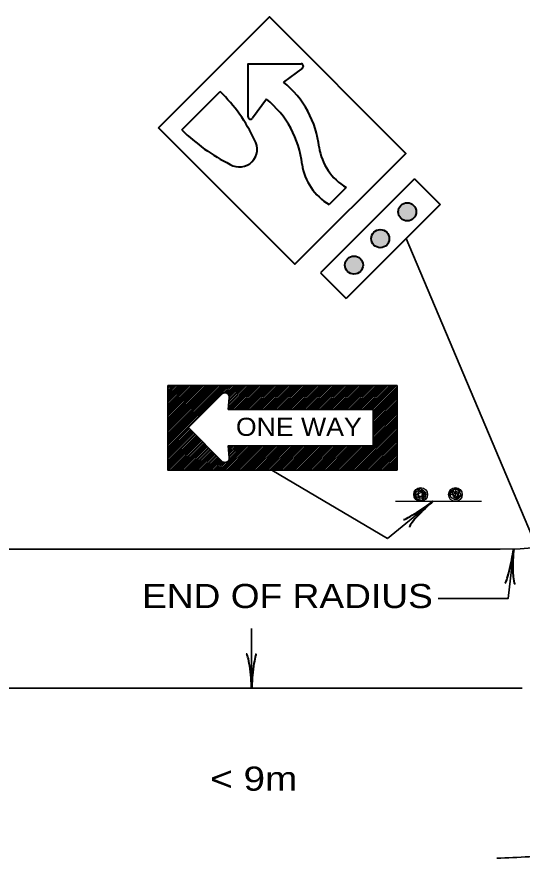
# Model space of a CAD drawing. Extents: x 1081 to 1936, y -630 to -24.
# Drawn here: x 1632.2 to 1682.5, y -218.3 to -134.7 of the extents above; entities that cross this region are included whole.
import ezdxf
from ezdxf.enums import TextEntityAlignment as Align

# ---------------------------------------------------------------- set-up
doc = ezdxf.new("R2010")
doc.units = 0
doc.layers.add('1', color=7, linetype='Continuous', lineweight=53)
doc.layers.add('4', color=7, linetype='Continuous', lineweight=25)

msp = doc.modelspace()

# ---------------------------------------------------------------- hatches: boundary and pattern name
at = {"layer": '1'}
for points in [[(1671.033, -153.186, 1), (1671.033, -154.986, 1)], [(1668.35, -155.851, 1), (1668.35, -157.651, 1)], [(1665.735, -158.482, 1), (1665.735, -160.282, 1)]]:
    msp.add_hatch(color=256, dxfattribs=at).paths.add_polyline_path(points)

# ---------------------------------------------------------------- linework, layer by layer
at = {"layer": '1', "lineweight": 40}
for p, q in [((1660.613, -139.797), (1658.724, -141.191)), ((1648.625, -145.94), (1652.443, -142.122)), ((1657.027, -142.888), (1655.634, -144.777)), ((1671.747, -150.82), (1662.413, -160.153)), ((1671.747, -150.82), (1674.292, -153.365)), ((1664.959, -151.668), (1663.262, -153.365)), ((1674.292, -153.365), (1664.959, -162.699)), ((1662.413, -160.153), (1664.959, -162.699))]:
    msp.add_line(p, q, dxfattribs=at)
at = {"layer": '1', "lineweight": 35}
for p, q in [((1696.877, -218.196), (1670.926, -156.732)), ((1647.222, -171.361), (1647.224, -171.359)), ((1647.222, -171.53), (1647.394, -171.359)), ((1647.222, -171.7), (1647.563, -171.359)), ((1647.222, -171.87), (1647.733, -171.359)), ((1647.222, -172.039), (1647.903, -171.359)), ((1647.222, -172.209), (1648.072, -171.359)), ((1647.222, -172.379), (1648.242, -171.359)), ((1647.222, -172.548), (1648.412, -171.359)), ((1647.222, -172.718), (1648.582, -171.359)), ((1647.222, -172.888), (1648.751, -171.359)), ((1647.222, -173.058), (1648.921, -171.359)), ((1647.222, -173.227), (1649.091, -171.359)), ((1647.222, -173.397), (1649.26, -171.359)), ((1647.222, -173.567), (1649.43, -171.359)), ((1647.222, -173.736), (1649.6, -171.359)), ((1647.222, -173.906), (1649.769, -171.359)), ((1647.222, -174.076), (1649.939, -171.359)), ((1647.222, -174.246), (1650.109, -171.359)), ((1647.222, -174.415), (1650.279, -171.359)), ((1647.222, -174.585), (1650.448, -171.359)), ((1647.222, -174.755), (1650.618, -171.359)), ((1647.222, -174.924), (1650.788, -171.359)), ((1647.222, -175.094), (1650.957, -171.359)), ((1647.222, -175.264), (1651.127, -171.359)), ((1647.222, -175.433), (1651.297, -171.359)), ((1647.222, -175.603), (1651.466, -171.359)), ((1647.222, -175.773), (1651.636, -171.359)), ((1647.222, -175.942), (1651.806, -171.359)), ((1647.222, -176.112), (1651.976, -171.359)), ((1647.222, -176.282), (1652.145, -171.359)), ((1647.222, -176.452), (1652.315, -171.359)), ((1647.222, -176.621), (1652.485, -171.359)), ((1647.222, -176.791), (1652.654, -171.359)), ((1647.222, -176.961), (1652.824, -171.359)), ((1647.222, -177.131), (1652.994, -171.359)), ((1647.222, -177.3), (1653.164, -171.359)), ((1647.222, -177.47), (1653.333, -171.359)), ((1652.758, -172.104), (1653.503, -171.359)), ((1652.949, -172.082), (1653.673, -171.359)), ((1653.082, -172.119), (1653.842, -171.359)), ((1653.186, -172.185), (1654.012, -171.359)), ((1653.24, -173.658), (1655.539, -171.359)), ((1653.257, -173.472), (1655.37, -171.359)), ((1653.266, -172.275), (1654.182, -171.359)), ((1653.273, -173.286), (1655.2, -171.359)), ((1653.289, -173.1), (1655.03, -171.359)), ((1653.305, -172.914), (1654.861, -171.359)), ((1653.32, -172.391), (1654.351, -171.359)), ((1653.322, -172.728), (1654.691, -171.359)), ((1653.331, -173.737), (1655.709, -171.359)), ((1653.338, -172.542), (1654.521, -171.359)), ((1653.501, -173.737), (1655.879, -171.359)), ((1653.671, -173.737), (1656.049, -171.359)), ((1653.84, -173.737), (1656.218, -171.359)), ((1654.01, -173.737), (1656.388, -171.359)), ((1654.18, -173.737), (1656.558, -171.359)), ((1654.349, -173.737), (1656.727, -171.359)), ((1654.519, -173.737), (1656.897, -171.359)), ((1654.689, -173.737), (1657.067, -171.359)), ((1654.858, -173.737), (1657.236, -171.359)), ((1655.028, -173.737), (1657.406, -171.359)), ((1655.198, -173.737), (1657.576, -171.359)), ((1655.368, -173.737), (1657.746, -171.359)), ((1655.537, -173.737), (1657.915, -171.359)), ((1655.707, -173.737), (1658.085, -171.359)), ((1655.877, -173.737), (1658.255, -171.359)), ((1656.046, -173.737), (1658.424, -171.359)), ((1656.216, -173.737), (1658.594, -171.359)), ((1656.386, -173.737), (1658.764, -171.359)), ((1656.555, -173.737), (1658.934, -171.359)), ((1656.725, -173.737), (1659.103, -171.359)), ((1656.895, -173.737), (1659.273, -171.359)), ((1657.065, -173.737), (1659.443, -171.359)), ((1657.234, -173.737), (1659.612, -171.359)), ((1657.404, -173.737), (1659.782, -171.359)), ((1657.574, -173.737), (1659.952, -171.359)), ((1657.743, -173.737), (1660.121, -171.359)), ((1657.913, -173.737), (1660.291, -171.359)), ((1658.083, -173.737), (1660.461, -171.359)), ((1658.253, -173.737), (1660.631, -171.359)), ((1658.422, -173.737), (1660.8, -171.359)), ((1658.592, -173.737), (1660.97, -171.359)), ((1658.762, -173.737), (1661.14, -171.359)), ((1658.931, -173.737), (1661.309, -171.359)), ((1659.101, -173.737), (1661.479, -171.359)), ((1659.271, -173.737), (1661.649, -171.359)), ((1659.44, -173.737), (1661.819, -171.359)), ((1659.61, -173.737), (1661.988, -171.359)), ((1659.78, -173.737), (1662.158, -171.359)), ((1659.95, -173.737), (1662.328, -171.359)), ((1660.119, -173.737), (1662.497, -171.359)), ((1660.289, -173.737), (1662.667, -171.359)), ((1660.459, -173.737), (1662.837, -171.359)), ((1660.628, -173.737), (1663.007, -171.359)), ((1660.798, -173.737), (1663.176, -171.359)), ((1660.968, -173.737), (1663.346, -171.359)), ((1661.138, -173.737), (1663.516, -171.359)), ((1661.307, -173.737), (1663.685, -171.359)), ((1661.477, -173.737), (1663.855, -171.359)), ((1661.647, -173.737), (1664.025, -171.359)), ((1661.816, -173.737), (1664.194, -171.359)), ((1661.986, -173.737), (1664.364, -171.359)), ((1662.156, -173.737), (1664.534, -171.359)), ((1662.325, -173.737), (1664.704, -171.359)), ((1662.495, -173.737), (1664.873, -171.359)), ((1662.665, -173.737), (1665.043, -171.359)), ((1662.835, -173.737), (1665.213, -171.359)), ((1663.004, -173.737), (1665.382, -171.359)), ((1663.174, -173.737), (1665.552, -171.359)), ((1663.344, -173.737), (1665.722, -171.359)), ((1663.513, -173.737), (1665.892, -171.359)), ((1663.683, -173.737), (1666.061, -171.359)), ((1663.853, -173.737), (1666.231, -171.359)), ((1664.023, -173.737), (1666.401, -171.359)), ((1664.192, -173.737), (1666.57, -171.359)), ((1664.362, -173.737), (1666.74, -171.359)), ((1664.532, -173.737), (1666.91, -171.359)), ((1664.701, -173.737), (1667.079, -171.359)), ((1664.871, -173.737), (1667.249, -171.359)), ((1665.041, -173.737), (1667.419, -171.359)), ((1665.21, -173.737), (1667.589, -171.359)), ((1665.38, -173.737), (1667.758, -171.359)), ((1665.55, -173.737), (1667.928, -171.359)), ((1665.72, -173.737), (1668.098, -171.359)), ((1665.889, -173.737), (1668.267, -171.359)), ((1666.059, -173.737), (1668.437, -171.359)), ((1666.229, -173.737), (1668.607, -171.359)), ((1666.398, -173.737), (1668.777, -171.359)), ((1666.568, -173.737), (1668.946, -171.359)), ((1666.738, -173.737), (1669.116, -171.359)), ((1666.908, -173.737), (1669.286, -171.359)), ((1667.077, -173.737), (1669.455, -171.359)), ((1667.247, -173.737), (1669.625, -171.359)), ((1667.417, -173.737), (1669.795, -171.359)), ((1667.586, -173.737), (1669.964, -171.359)), ((1667.633, -173.859), (1670.022, -171.471)), ((1649.282, -175.537), (1652.676, -172.143)), ((1667.633, -174.029), (1670.022, -171.64)), ((1667.633, -174.199), (1670.022, -171.81)), ((1667.633, -174.369), (1670.022, -171.98)), ((1667.633, -174.538), (1670.022, -172.15)), ((1667.633, -174.708), (1670.022, -172.319)), ((1667.633, -174.878), (1670.022, -172.489)), ((1667.633, -175.048), (1670.022, -172.659)), ((1667.633, -175.217), (1670.022, -172.828)), ((1667.633, -175.387), (1670.022, -172.998)), ((1667.633, -175.557), (1670.022, -173.168)), ((1667.633, -175.726), (1670.022, -173.338)), ((1667.633, -175.896), (1670.022, -173.507)), ((1667.633, -176.066), (1670.022, -173.677)), ((1667.633, -176.235), (1670.022, -173.847)), ((1667.633, -176.405), (1670.022, -174.016)), ((1667.633, -176.575), (1670.022, -174.186)), ((1667.633, -176.745), (1670.022, -174.356)), ((1667.633, -176.914), (1670.022, -174.525)), ((1667.633, -177.084), (1670.022, -174.695)), ((1647.222, -177.64), (1649.303, -175.558)), ((1647.222, -177.809), (1649.388, -175.643)), ((1652.676, -178.931), (1649.282, -175.537)), ((1665.298, -179.759), (1670.022, -175.035)), ((1665.468, -179.759), (1670.022, -175.204)), ((1665.637, -179.759), (1670.022, -175.374)), ((1665.807, -179.759), (1670.022, -175.544)), ((1667.633, -177.254), (1670.022, -174.865)), ((1647.222, -177.979), (1649.473, -175.728)), ((1647.222, -178.149), (1649.558, -175.813)), ((1647.222, -178.318), (1649.643, -175.898)), ((1647.222, -178.488), (1649.728, -175.983)), ((1647.222, -178.658), (1649.812, -176.067)), ((1647.222, -178.828), (1649.897, -176.152)), ((1647.222, -178.997), (1649.982, -176.237)), ((1647.222, -179.167), (1650.067, -176.322)), ((1647.222, -179.337), (1650.152, -176.407)), ((1647.222, -179.506), (1650.237, -176.492)), ((1665.977, -179.759), (1670.022, -175.713)), ((1666.147, -179.759), (1670.022, -175.883)), ((1666.316, -179.759), (1670.022, -176.053)), ((1666.486, -179.759), (1670.022, -176.222)), ((1666.656, -179.759), (1670.022, -176.392)), ((1647.222, -179.676), (1650.322, -176.577)), ((1647.309, -179.759), (1650.407, -176.662)), ((1647.479, -179.759), (1650.491, -176.746)), ((1647.649, -179.759), (1650.576, -176.831)), ((1647.818, -179.759), (1650.661, -176.916)), ((1647.988, -179.759), (1650.746, -177.001)), ((1648.158, -179.759), (1650.831, -177.086)), ((1648.327, -179.759), (1650.916, -177.171)), ((1648.497, -179.759), (1651, -177.255)), ((1648.667, -179.759), (1651.085, -177.34)), ((1652.4, -179.759), (1654.822, -177.337)), ((1652.57, -179.759), (1654.992, -177.337)), ((1652.74, -179.759), (1655.162, -177.337)), ((1652.909, -179.759), (1655.331, -177.337)), ((1653.079, -179.759), (1655.501, -177.337)), ((1653.238, -177.393), (1653.295, -177.337)), ((1653.249, -179.759), (1655.671, -177.337)), ((1653.252, -177.549), (1653.465, -177.337)), ((1653.266, -177.706), (1653.634, -177.337)), ((1653.279, -177.862), (1653.804, -177.337)), ((1653.293, -178.018), (1653.974, -177.337)), ((1653.307, -178.174), (1654.143, -177.337)), ((1653.32, -178.33), (1654.313, -177.337)), ((1653.326, -178.664), (1654.653, -177.337)), ((1653.334, -178.486), (1654.483, -177.337)), ((1653.418, -179.759), (1655.84, -177.337)), ((1653.588, -179.759), (1656.01, -177.337)), ((1653.758, -179.759), (1656.18, -177.337)), ((1653.928, -179.759), (1656.35, -177.337)), ((1654.097, -179.759), (1656.519, -177.337)), ((1654.267, -179.759), (1656.689, -177.337)), ((1654.437, -179.759), (1656.859, -177.337)), ((1654.607, -179.759), (1657.028, -177.337)), ((1654.776, -179.759), (1657.198, -177.337)), ((1654.946, -179.759), (1657.368, -177.337)), ((1655.116, -179.759), (1657.538, -177.337)), ((1655.285, -179.759), (1657.707, -177.337)), ((1655.455, -179.759), (1657.877, -177.337)), ((1655.625, -179.759), (1658.047, -177.337)), ((1655.794, -179.759), (1658.216, -177.337)), ((1655.964, -179.759), (1658.386, -177.337)), ((1656.134, -179.759), (1658.556, -177.337)), ((1656.303, -179.759), (1658.725, -177.337)), ((1656.473, -179.759), (1658.895, -177.337)), ((1656.643, -179.759), (1659.065, -177.337)), ((1656.813, -179.759), (1659.235, -177.337)), ((1656.982, -179.759), (1659.404, -177.337)), ((1657.152, -179.759), (1659.574, -177.337)), ((1657.322, -179.759), (1659.744, -177.337)), ((1657.492, -179.759), (1659.913, -177.337)), ((1657.661, -179.759), (1660.083, -177.337)), ((1657.831, -179.759), (1660.253, -177.337)), ((1658.001, -179.759), (1660.423, -177.337)), ((1658.17, -179.759), (1660.592, -177.337)), ((1658.34, -179.759), (1660.762, -177.337)), ((1658.51, -179.759), (1660.932, -177.337)), ((1658.679, -179.759), (1661.101, -177.337)), ((1658.849, -179.759), (1661.271, -177.337)), ((1659.019, -179.759), (1661.441, -177.337)), ((1659.188, -179.759), (1661.61, -177.337)), ((1659.358, -179.759), (1661.78, -177.337)), ((1659.528, -179.759), (1661.95, -177.337)), ((1659.698, -179.759), (1662.12, -177.337)), ((1659.867, -179.759), (1662.289, -177.337)), ((1660.037, -179.759), (1662.459, -177.337)), ((1660.207, -179.759), (1662.629, -177.337)), ((1660.377, -179.759), (1662.798, -177.337)), ((1660.546, -179.759), (1662.968, -177.337)), ((1660.716, -179.759), (1663.138, -177.337)), ((1660.886, -179.759), (1663.308, -177.337)), ((1661.055, -179.759), (1663.477, -177.337)), ((1661.225, -179.759), (1663.647, -177.337)), ((1661.395, -179.759), (1663.817, -177.337)), ((1661.564, -179.759), (1663.986, -177.337)), ((1661.734, -179.759), (1664.156, -177.337)), ((1661.904, -179.759), (1664.326, -177.337)), ((1662.073, -179.759), (1664.495, -177.337)), ((1662.243, -179.759), (1664.665, -177.337)), ((1662.413, -179.759), (1664.835, -177.337)), ((1662.583, -179.759), (1665.005, -177.337)), ((1662.752, -179.759), (1665.174, -177.337)), ((1662.922, -179.759), (1665.344, -177.337)), ((1663.092, -179.759), (1665.514, -177.337)), ((1663.262, -179.759), (1665.683, -177.337)), ((1663.431, -179.759), (1665.853, -177.337)), ((1663.601, -179.759), (1666.023, -177.337)), ((1663.771, -179.759), (1666.193, -177.337)), ((1663.94, -179.759), (1666.362, -177.337)), ((1664.11, -179.759), (1666.532, -177.337)), ((1664.28, -179.759), (1666.702, -177.337)), ((1664.449, -179.759), (1666.871, -177.337)), ((1664.619, -179.759), (1667.041, -177.337)), ((1664.789, -179.759), (1667.211, -177.337)), ((1664.959, -179.759), (1667.38, -177.337)), ((1665.128, -179.759), (1667.55, -177.337)), ((1666.825, -179.759), (1670.022, -176.562)), ((1666.995, -179.759), (1670.022, -176.732)), ((1667.165, -179.759), (1670.022, -176.901)), ((1667.334, -179.759), (1670.022, -177.071)), ((1667.504, -179.759), (1670.022, -177.241)), ((1648.837, -179.759), (1651.17, -177.425)), ((1649.006, -179.759), (1651.255, -177.51)), ((1649.176, -179.759), (1651.34, -177.595)), ((1649.346, -179.759), (1651.425, -177.68)), ((1649.515, -179.759), (1651.51, -177.765)), ((1649.685, -179.759), (1651.594, -177.849)), ((1649.855, -179.759), (1651.679, -177.934)), ((1650.024, -179.759), (1651.764, -178.019)), ((1650.194, -179.759), (1651.849, -178.104)), ((1667.674, -179.759), (1670.022, -177.41)), ((1667.844, -179.759), (1670.022, -177.58)), ((1668.013, -179.759), (1670.022, -177.75)), ((1668.183, -179.759), (1670.022, -177.919)), ((1668.353, -179.759), (1670.022, -178.089)), ((1650.364, -179.759), (1651.934, -178.189)), ((1650.534, -179.759), (1652.019, -178.274)), ((1650.703, -179.759), (1652.104, -178.359)), ((1650.873, -179.759), (1652.188, -178.443)), ((1651.043, -179.759), (1652.273, -178.528)), ((1651.212, -179.759), (1652.358, -178.613)), ((1651.382, -179.759), (1652.443, -178.698)), ((1651.552, -179.759), (1652.528, -178.783)), ((1651.722, -179.759), (1652.613, -178.868)), ((1651.891, -179.759), (1652.704, -178.946)), ((1652.061, -179.759), (1652.831, -178.988)), ((1652.231, -179.759), (1653.009, -178.981)), ((1668.522, -179.759), (1670.022, -178.259)), ((1668.692, -179.759), (1670.022, -178.429)), ((1668.862, -179.759), (1670.022, -178.598)), ((1669.032, -179.759), (1670.022, -178.768)), ((1669.201, -179.759), (1670.022, -178.938)), ((1669.067, -186.581), (1657.577, -179.759)), ((1669.371, -179.759), (1670.022, -179.108)), ((1669.541, -179.759), (1670.022, -179.277)), ((1669.71, -179.759), (1670.022, -179.447)), ((1669.88, -179.759), (1670.022, -179.617)), ((1669.067, -186.581), (1673.61, -182.855)), ((1541.672, -187.636), (1680.28, -187.636)), ((1655.548, -201.506), (1655.548, -195.506)), ((1541.672, -201.46), (1682.457, -201.46))]:
    msp.add_line(p, q, dxfattribs=at)
at = {"layer": '1', "lineweight": 25}
msp.add_line((1669.852, -182.855), (1678.42, -182.855), dxfattribs=at)
at = {"layer": '1', "lineweight": 40}
msp.add_lwpolyline([(1646.291, -145.728), (1657.322, -134.697), (1670.899, -148.274), (1659.868, -159.305)], close=True, dxfattribs=at)
msp.add_lwpolyline([(1655.201, -144.634), (1655.201, -139.364), (1660.471, -139.364)], dxfattribs=at)
at = {"layer": '1', "lineweight": 35}
msp.add_lwpolyline([(1647.222, -171.359), (1670.022, -171.359), (1670.022, -179.759), (1647.222, -179.759)], close=True, dxfattribs=at)
for points in [[(1653.338, -172.542), (1653.233, -173.737), (1667.633, -173.737), (1667.633, -177.337), (1653.233, -177.337), (1653.338, -178.532)], [(1674.105, -192.529), (1681.066, -192.529), (1681.617, -187.619)]]:
    msp.add_lwpolyline(points, dxfattribs=at)
at = {"layer": '1', "lineweight": 40}
for centre in [(1671.033, -154.086), (1668.35, -156.751), (1665.735, -159.382)]:
    msp.add_circle(centre, 0.9, dxfattribs=at)
for centre, radius, start, end in [((1660.471, -139.604), 0.24, 306.40525, 90), ((1652.706, -148.692), 9.617, 6.10806, 51.26016), ((1640.829, -154.031), 16.618, 25.28501, 45.72037), ((1651.009, -150.389), 9.617, 6.10806, 51.26016), ((1655.441, -144.634), 0.24, 179.99403, 323.59761), ((1661.755, -132.611), 18.71, 225.43251, 243.56211), ((1654.345, -147.855), 1.769, 238.60951, 31.39048), ((1667.839, -146.825), 5.635, 188.60534, 239.2536), ((1666.142, -148.522), 5.635, 188.60534, 239.2536)]:
    msp.add_arc(centre, radius, start, end, dxfattribs=at)
at = {"layer": '1', "lineweight": 35}
for centre, radius, start, end in [((1680.28, -149.235), 38.4, 270, 0), ((1652.902, -172.516), 0.436, 356.63551, 121.23355), ((1652.902, -178.558), 0.436, 238.76645, 3.36449), ((1678.954, -162.338), 56.019, 271.0058, 277.57279)]:
    msp.add_arc(centre, radius, start, end, dxfattribs=at)
at = {"layer": '1', "lineweight": 40}
for centre, major_axis, ratio, start_param, end_param in [((1672.409, -183.511), (-1.763, -1.174), 0.07063, 6.282307, 8.559703), ((1672.808, -183.941), (1.538, 1.504), 0.122415, 0.896353, 3.141593), ((1681.215, -188.927), (0.445, 2.071), 0.07063, 3.140715, 5.41811), ((1681.215, -188.927), (0.445, 2.071), 0.07063, 3.140715, 5.41811), ((1681.8, -188.957), (0.053, 2.15), 0.122415, 0.896353, 3.141593), ((1681.8, -188.957), (0.053, 2.15), 0.122415, 0.896353, 3.141593), ((1655.216, -200.196), (0.187, -2.143), 0.122415, 0.896353, 3.141593), ((1655.802, -200.161), (-0.211, -2.108), 0.07063, 3.140715, 5.41811)]:
    msp.add_ellipse(centre, major_axis=major_axis, ratio=ratio, start_param=start_param, end_param=end_param, dxfattribs=at)
at = {"layer": '1', "lineweight": 25}
for points in [[(1675.765, -182.72), (1675.43, -182.485), (1675.262, -182.149), (1675.362, -181.914), (1675.732, -181.679), (1676.101, -181.679), (1676.471, -182.048), (1676.236, -182.485), (1675.765, -182.72), (1675.564, -182.586), (1675.396, -182.485), (1675.329, -182.183), (1675.564, -181.779), (1675.698, -181.611), (1676.169, -181.88), (1676.101, -182.216), (1676.034, -182.418), (1675.9, -182.485), (1675.698, -182.485), (1675.598, -182.283), (1675.564, -181.914), (1675.799, -181.914), (1675.967, -181.88), (1676.101, -182.082), (1675.866, -182.384), (1675.665, -182.25), (1675.631, -182.115), (1675.866, -182.082), (1675.833, -182.015), (1676.337, -182.384), (1675.9, -181.578), (1675.799, -182.048), (1675.497, -181.746), (1675.161, -182.216), (1675.866, -182.082), (1675.732, -182.519), (1676.202, -182.418), (1675.866, -182.082)], [(1672.372, -182.787), (1672.002, -182.619), (1671.767, -182.25), (1671.834, -181.847), (1672.271, -181.578), (1672.674, -181.813), (1672.909, -182.149), (1672.842, -182.384), (1672.372, -182.787), (1672.137, -182.519), (1671.935, -182.418), (1671.902, -182.216), (1672.137, -181.746), (1672.372, -181.779), (1672.54, -181.914), (1672.809, -182.082), (1672.607, -182.485), (1672.338, -182.552), (1672.17, -182.418), (1672.07, -182.216), (1672.137, -182.015), (1672.204, -181.88), (1672.54, -181.981), (1672.473, -182.216), (1672.473, -182.351), (1672.204, -182.351), (1672.137, -182.149), (1672.506, -182.015), (1672.573, -182.048), (1672.876, -182.351), (1672.439, -181.712), (1672.54, -182.015), (1672.036, -181.679), (1671.801, -182.25), (1672.506, -182.015), (1672.54, -182.619), (1672.641, -182.485), (1672.506, -182.015)]]:
    msp.add_spline(points, degree=3, dxfattribs=at)
at = {"layer": '4'}
for centre in [(1672.364, -182.194), (1675.819, -182.193)]:
    msp.add_circle(centre, 0.689, dxfattribs=at)

# ---------------------------------------------------------------- texts
at = {"layer": '1'}
for s, height, width, p in [('ONE WAY', 1.8, 1.1, (1660.25, -176.36)), ('END OF RADIUS', 2.4, 1.15, (1659.118, -193.483)), ('< 9m', 2.4, 1.2, (1655.77, -211.641))]:
    msp.add_text(s, height=height, dxfattribs=dict(at, width=width)).set_placement(p, align=Align.CENTER)

doc.saveas('drawing.dxf')
